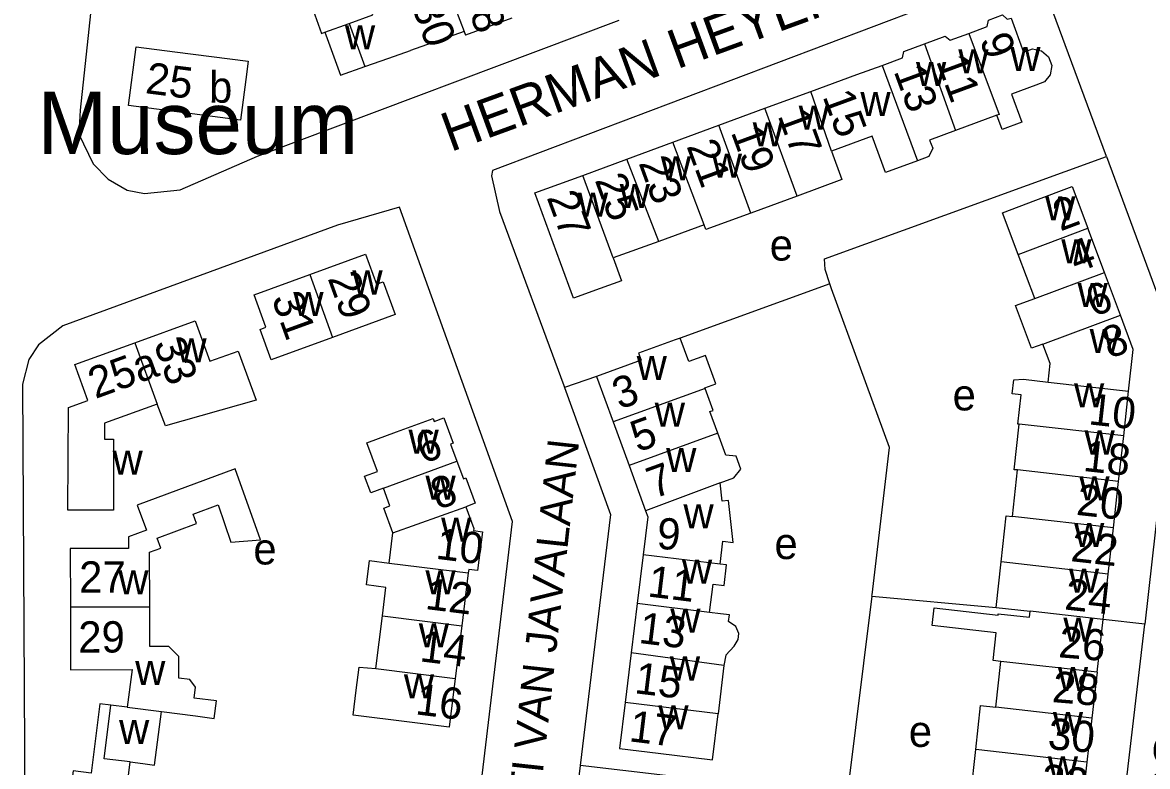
# Model space of a CAD drawing. Extents: x 161258 to 163262, y 380749 to 382054.
# Drawn here: x 161563.2 to 161707.1, y 381384.9 to 381480.1 of the extents above; entities that cross this region are included whole.
import ezdxf

# ---------------------------------------------------------------- set-up
doc = ezdxf.new("R2010")
doc.units = 0
for name, color, linetype in [('BLT_Basislijn', 7, 'Continuous'), ('BLT_Bebouwing', 7, 'Continuous'), ('BLT_Bebouwing_beschrifting', 7, 'Continuous'), ('BLT_Centroide', 7, 'Continuous'), ('BLT_Huisnummer', 7, 'Continuous'), ('BLT_Huisnummer_ tussenligend', 7, 'Continuous'), ('BLT_Onderverdeling_panden', 7, 'Continuous'), ('BLT_Straatnaam', 7, 'Continuous'), ('BLT_Straatnaam_verkleind', 7, 'Continuous')]:
    doc.layers.add(name, color=color, linetype=linetype)

msp = doc.modelspace()

# ---------------------------------------------------------------- linework, layer by layer
at = {"layer": 'BLT_Basislijn'}
for p, q in [((161666.45, 381446.68), (161647.33, 381439.73)), ((161636.63, 381434.83), (161632.51, 381433.43)), ((161671.84, 381406.71), (161687.71, 381405.27)), ((161706.75, 381403.16), (161701.39, 381403.74))]:
    msp.add_line(p, q, dxfattribs=at)
for points in [[(161647.76, 381582.3), (161646.86, 381582.41), (161591.08, 381589.63), (161587.77, 381589.77), (161586.23, 381588.91), (161584.89, 381586.68), (161583.08, 381574.39), (161573.92, 381500), (161570.58, 381468.89), (161570.42, 381465.8), (161572.24, 381462.03), (161574.18, 381460.03), (161576.58, 381458.66), (161578.81, 381458.22), (161583.37, 381458.7), (161593.26, 381463), (161639.49, 381480.37)], [(161701.85, 381462.93), (161692.96, 381486.95), (161678.18, 381481.89), (161623.33, 381461.17), (161623.17, 381460.48), (161624.21, 381455.92), (161632.42, 381433.68), (161632.51, 381433.43)], [(161666.45, 381446.68), (161665.84, 381448.48), (161665.78, 381449.87), (161701.85, 381462.93)], [(161701.85, 381462.93), (161710.73, 381438.82), (161706.75, 381403.16)], [(161619.38, 381362.01), (161625.85, 381416.26), (161611.4, 381456.47), (161603.5, 381454.17), (161568.37, 381441.3), (161565.27, 381438.88), (161564, 381436.97), (161563.2, 381433.85), (161563.56, 381371.71), (161565.42, 381369.4), (161568.4, 381368.11), (161592.1, 381365.28)], [(161671.84, 381406.71), (161671.86, 381406.88), (161674.07, 381425.72), (161666.67, 381446.04), (161666.45, 381446.68)], [(161632.51, 381433.43), (161638.42, 381417.16), (161634.53, 381385.07)], [(161671.84, 381406.71), (161668.65, 381381.35), (161667.24, 381381.25), (161634.53, 381385.07)], [(161634.53, 381385.07), (161631.61, 381361.46), (161631.65, 381360.05), (161700.74, 381351.9), (161706.75, 381403.16)]]:
    msp.add_lwpolyline(points, dxfattribs=at)
at = {"layer": 'BLT_Bebouwing'}
for p, q in [((161625.77, 381480.65), (161619.84, 381478.48)), ((161619.67, 381478.94), (161612.82, 381476.51)), ((161619.67, 381478.94), (161619.84, 381478.48)), ((161658.14, 381469.11), (161664.02, 381471.27)), ((161652.25, 381466.94), (161658.14, 381469.11)), ((161687.82, 381468.23), (161682.54, 381466.28)), ((161646.37, 381464.78), (161652.25, 381466.94)), ((161640.49, 381462.62), (161646.37, 381464.78)), ((161634.85, 381460.54), (161640.49, 381462.62)), ((161662.28, 381457.89), (161656.34, 381455.71)), ((161650.38, 381454.19), (161644.57, 381452.06)), ((161701.56, 381448.13), (161699.46, 381453.77)), ((161692.65, 381444.8), (161690.54, 381450.42)), ((161703.61, 381442.65), (161701.56, 381448.13)), ((161636.63, 381434.83), (161638.75, 381429.02)), ((161704.03, 381427.22), (161704.66, 381432.94)), ((161638.75, 381429.02), (161640.77, 381423.45)), ((161640.77, 381423.45), (161642.88, 381417.62)), ((161689.81, 381416.92), (161690.47, 381422.86)), ((161702.71, 381415.47), (161703.38, 381421.41)), ((161642.88, 381417.62), (161643.16, 381416.86)), ((161643.16, 381416.86), (161642.57, 381412.02)), ((161610.08, 381410.96), (161610.56, 381414.84)), ((161702.05, 381409.56), (161702.71, 381415.47)), ((161642.57, 381412.02), (161641.81, 381405.78)), ((161620.21, 381409.7), (161619.37, 381402.95)), ((161701.39, 381403.74), (161702.05, 381409.56)), ((161641.81, 381405.78), (161641.04, 381399.46)), ((161687.71, 381405.27), (161692.05, 381404.79)), ((161608.4, 381397.46), (161609.24, 381404.21)), ((161700.63, 381397.01), (161701.39, 381403.74)), ((161619.37, 381402.95), (161618.53, 381396.2)), ((161641.04, 381399.46), (161640.27, 381393.11)), ((161652.9, 381397.84), (161652.15, 381391.66)), ((161687.69, 381392.52), (161688.34, 381398.39)), ((161700.63, 381397.01), (161699.97, 381391.14)), ((161576.61, 381392.52), (161574.51, 381392.78)), ((161699.97, 381391.14), (161699.33, 381385.5)), ((161575.95, 381377.48), (161576.97, 381385.52))]:
    msp.add_line(p, q, dxfattribs=at)
for points in [[(161608.01, 381481.08), (161606.93, 381484.05), (161600.37, 381481.65), (161601.45, 381478.68), (161601.88, 381478.84)], [(161684.21, 381478.67), (161686.59, 381479.56), (161686.73, 381480.39), (161688.53, 381481.05), (161689.15, 381480.53), (161689.63, 381480.66), (161691.23, 381476.29)], [(161601.88, 381478.84), (161602.16, 381478.02), (161603.88, 381473.33), (161606.99, 381474.44)], [(161678.55, 381477.34), (161681.21, 381478.32), (161681.82, 381477.81), (161684.21, 381478.67)], [(161591.76, 381472.79), (161591.1, 381467.61), (161576.78, 381469.45), (161577.74, 381476.96), (161582.7, 381476.33), (161592.06, 381475.13), (161591.76, 381472.79)], [(161610.04, 381475.52), (161612.82, 381476.51)], [(161673.16, 381474.6), (161675.76, 381475.55), (161675.9, 381476.37), (161678.55, 381477.34)], [(161691.23, 381476.29), (161692.36, 381476.71), (161693.53, 381476.48), (161694.43, 381475.71), (161694.85, 381474.58), (161694.65, 381473.41), (161693.91, 381472.48), (161692.79, 381472.07), (161689.67, 381470.92), (161690.99, 381467.33), (161688.49, 381466.41), (161687.82, 381468.23)], [(161606.99, 381474.44), (161610.04, 381475.52)], [(161664.02, 381471.27), (161669.89, 381473.43), (161673.16, 381474.6)], [(161677.65, 381462.39), (161673.58, 381460.89), (161671.87, 381465.56), (161666.66, 381463.64)], [(161682.54, 381466.28), (161679.18, 381465.04), (161679.61, 381464.02), (161679.11, 381462.93), (161677.65, 381462.39)], [(161666.66, 381463.64), (161668, 381459.99), (161662.28, 381457.89)], [(161638.75, 381449.97), (161639.82, 381447.07), (161637.1, 381446.08), (161633.68, 381444.82), (161632.01, 381449.36), (161628.73, 381458.29), (161634.85, 381460.54)], [(161690.54, 381450.42), (161688.53, 381455.76), (161692.78, 381457.36), (161697.46, 381459.12), (161699.46, 381453.77)], [(161656.34, 381455.71), (161650.6, 381453.6), (161650.38, 381454.19)], [(161644.57, 381452.06), (161638.75, 381449.97)], [(161599.94, 381447.87), (161607.07, 381450.46), (161608.46, 381446.62), (161609.33, 381446.94), (161610.86, 381442.73), (161602.86, 381439.82)], [(161602.86, 381439.82), (161594.99, 381436.96), (161593.58, 381440.84), (161594.32, 381441.11), (161592.81, 381445.28), (161599.94, 381447.87)], [(161693.71, 381438.96), (161692.26, 381438.42), (161690.2, 381443.89), (161692.65, 381444.8)], [(161704.66, 381432.94), (161705.25, 381438.25), (161703.61, 381442.65)], [(161577.59, 381439.13), (161585.3, 381441.92), (161587, 381437.23), (161587.17, 381436.77), (161590.8, 381438.07), (161593.08, 381431.81), (161581.48, 381428.49), (161580.44, 381431.29)], [(161580.44, 381431.29), (161573.71, 381428.85), (161573.71, 381426.81), (161574.84, 381426.82), (161574.85, 381417.73), (161573.99, 381417.73), (161568.99, 381417.72), (161569.09, 381430.85), (161571.56, 381431.74), (161569.89, 381436.33), (161577.59, 381439.13)], [(161647.33, 381439.73), (161646.69, 381439.49), (161641.99, 381437.79), (161642.31, 381436.89), (161636.63, 381434.83)], [(161650.5, 381433.28), (161650.47, 381433.35), (161651.87, 381433.86), (161650.55, 381437.5), (161648.42, 381436.73), (161647.33, 381439.73)], [(161694.37, 381434.1), (161694.64, 381436.49), (161693.71, 381438.96)], [(161690.68, 381428.72), (161690.48, 381428.74), (161690.9, 381432.47), (161689.77, 381432.59), (161689.97, 381434.4), (161691.2, 381434.46), (161694.37, 381434.1)], [(161652.12, 381427.56), (161651.11, 381430.34), (161651.51, 381430.48), (161650.5, 381433.28)], [(161609.38, 381420.54), (161607.73, 381419.93), (161606.94, 381422.07), (161608.59, 381422.67), (161607.24, 381426.32), (161611.03, 381427.72), (161615.72, 381429.45), (161615.86, 381429.08), (161617.09, 381429.53), (161618.29, 381426.3), (161617.96, 381426.18), (161618.76, 381424)], [(161690.47, 381422.86), (161690.04, 381422.9), (161690.68, 381428.72)], [(161652.42, 381421.22), (161654.18, 381421.86), (161655.05, 381422.98), (161654.47, 381424.62), (161653.13, 381424.76), (161652.12, 381427.56)], [(161703.38, 381421.41), (161704.03, 381427.22)], [(161618.76, 381424), (161619.59, 381421.72), (161619.91, 381421.84), (161621.1, 381418.6), (161619.89, 381418.16)], [(161579.47, 381405.3), (161579.46, 381412.34), (161580.89, 381412.87), (161580.42, 381414.15), (161585.47, 381416.03), (161585.03, 381417.21), (161588.21, 381418.39), (161589.84, 381413.64), (161593.65, 381413.93), (161590.41, 381423.02), (161577.88, 381418.37), (161579.07, 381415.15), (161576.77, 381414.3), (161576.77, 381412.82), (161569.32, 381412.81), (161569.33, 381405.3)], [(161610.56, 381414.84), (161609.4, 381418), (161610.2, 381418.29), (161609.38, 381420.54)], [(161652.42, 381410.82), (161652.77, 381413.75), (161654.11, 381413.57), (161653.48, 381418.97), (161652.69, 381418.88), (161652.42, 381421.22)], [(161619.89, 381418.16), (161620.92, 381415.36), (161620.89, 381415.13)], [(161688.35, 381411.1), (161689.01, 381417.01), (161689.81, 381416.92)], [(161620.89, 381415.13), (161622.04, 381414.97), (161621.38, 381409.99), (161620.27, 381410.13), (161620.21, 381409.7)], [(161609.24, 381404.21), (161609.69, 381407.85), (161607.21, 381408.17), (161607.6, 381411.27), (161610.08, 381410.96)], [(161651.07, 381404.65), (161651.51, 381408.24), (161652.93, 381408.07), (161653.25, 381410.72), (161652.42, 381410.82)], [(161687.71, 381405.27), (161688.35, 381411.1)], [(161569.33, 381405.3), (161569.34, 381397.32), (161577.23, 381397.34), (161576.61, 381392.52)], [(161580.96, 381391.96), (161585.31, 381391.41), (161587.73, 381391.1), (161588.01, 381393.34), (161585.15, 381393.7), (161585.33, 381395.08), (161584.61, 381396.08), (161583.2, 381396.26), (161583.2, 381399.02), (161581.9, 381400.31), (161579.48, 381400.3), (161579.47, 381405.3)], [(161654.22, 381400.32), (161654.73, 381401.18), (161654.8, 381401.97), (161654.42, 381402.85), (161653.51, 381403.47), (161653.62, 381404.34), (161652.46, 381404.48), (161651.07, 381404.65)], [(161688.34, 381398.39), (161687.32, 381398.5), (161687.71, 381402.03), (161679.54, 381402.96), (161679.8, 381405.24), (161687.96, 381404.31), (161687.98, 381404.47), (161691.97, 381404.02), (161692.05, 381404.79)], [(161654.22, 381400.32), (161653.13, 381399.17), (161652.9, 381397.84)], [(161618.53, 381396.2), (161617.76, 381389.99), (161612.68, 381390.62), (161605.49, 381391.51), (161605.88, 381394.71), (161606.25, 381397.65), (161608.4, 381397.46)], [(161640.27, 381393.11), (161639.55, 381387.24), (161644.51, 381386.63), (161651.43, 381385.79), (161652.15, 381391.66)], [(161573.1, 381392.96), (161571.97, 381384.09), (161569.68, 381384.38), (161569.05, 381379.42), (161567.99, 381379.55), (161567.23, 381373.55), (161575.32, 381372.52), (161575.95, 381377.48)], [(161574.51, 381392.78), (161573.1, 381392.96)], [(161576.97, 381385.52), (161578.6, 381385.31), (161580.09, 381385.12), (161580.96, 381391.96)], [(161685.11, 381387.1), (161685.73, 381392.73), (161687.69, 381392.52)], [(161699.33, 381385.5), (161698.69, 381379.75), (161693.72, 381380.3), (161689.48, 381380.77), (161689.32, 381379.38), (161684.31, 381379.93), (161684.47, 381381.32), (161685.11, 381387.1)]]:
    msp.add_lwpolyline(points, dxfattribs=at)
at = {"layer": 'BLT_Onderverdeling_panden'}
for p, q in [((161615.23, 381490.73), (161619.67, 381478.94)), ((161604.97, 381479.97), (161606.99, 381474.44)), ((161678.55, 381477.34), (161682.54, 381466.28)), ((161673.16, 381474.6), (161677.65, 381462.39)), ((161666.66, 381463.64), (161664.02, 381471.27)), ((161662.28, 381457.89), (161658.14, 381469.11)), ((161656.34, 381455.71), (161652.25, 381466.94)), ((161650.38, 381454.19), (161646.37, 381464.78)), ((161644.57, 381452.06), (161640.49, 381462.62)), ((161638.75, 381449.97), (161634.85, 381460.54)), ((161690.54, 381450.42), (161699.46, 381453.77)), ((161599.94, 381447.87), (161602.86, 381439.82)), ((161692.65, 381444.8), (161701.56, 381448.13)), ((161693.71, 381438.96), (161703.61, 381442.65)), ((161577.59, 381439.13), (161580.44, 381431.29)), ((161694.37, 381434.1), (161704.66, 381432.94)), ((161650.5, 381433.28), (161638.75, 381429.02)), ((161652.12, 381427.56), (161640.77, 381423.45)), ((161609.38, 381420.54), (161618.76, 381424)), ((161703.38, 381421.41), (161690.47, 381422.86)), ((161652.42, 381421.22), (161642.88, 381417.62)), ((161610.56, 381414.84), (161619.89, 381418.16)), ((161702.71, 381415.47), (161689.81, 381416.92)), ((161652.42, 381410.82), (161642.57, 381412.02)), ((161610.08, 381410.96), (161620.21, 381409.7)), ((161702.05, 381409.56), (161688.35, 381411.1)), ((161579.47, 381405.3), (161569.33, 381405.3)), ((161651.07, 381404.65), (161641.81, 381405.78)), ((161701.39, 381403.74), (161692.05, 381404.79)), ((161609.24, 381404.21), (161619.37, 381402.95)), ((161652.9, 381397.84), (161641.04, 381399.46)), ((161608.4, 381397.46), (161618.53, 381396.2)), ((161700.63, 381397.01), (161688.34, 381398.39)), ((161652.15, 381391.66), (161640.27, 381393.11)), ((161576.61, 381392.52), (161580.96, 381391.96)), ((161699.97, 381391.14), (161687.69, 381392.52)), ((161699.33, 381385.5), (161685.11, 381387.1))]:
    msp.add_line(p, q, dxfattribs=at)
for points in [[(161604.97, 381479.97), (161608.01, 381481.08)], [(161601.88, 381478.84), (161604.97, 381479.97)], [(161684.21, 381478.67), (161688.1, 381468.33), (161687.82, 381468.23)], [(161704.03, 381427.22), (161690.68, 381428.72)], [(161576.97, 381385.52), (161573.64, 381385.94), (161574.51, 381392.78)]]:
    msp.add_lwpolyline(points, dxfattribs=at)

# ---------------------------------------------------------------- texts
at = {"layer": 'BLT_Bebouwing_beschrifting'}
msp.add_text('Museum', height=8, dxfattribs=at).set_placement((161565.11, 381463.26))
at = {"layer": 'BLT_Centroide'}
for s, p in [('w', (161604.44, 381476.66)), ('w', (161682.88, 381473.58)), ('w', (161689.53, 381473.89)), ('b', (161587.06, 381469.83)), ('w', (161677.47, 381471.97)), ('w', (161670.36, 381468.12)), ('w', (161662.47, 381466.39)), ('w', (161656.59, 381464.23)), ('w', (161644.83, 381459.91)), ('w', (161651.36, 381460.25)), ('w', (161639.58, 381456.38)), ('w', (161634.23, 381455.25)), ('w', (161693.99, 381454.78)), ('e', (161658.76, 381449.64)), ('w', (161696.05, 381449.28)), ('w', (161605.39, 381445.3)), ('w', (161698.13, 381443.72)), ('w', (161597.84, 381442.55)), ('w', (161699.68, 381437.81)), ('w', (161582.88, 381436.61)), ('w', (161641.75, 381434.38)), ('e', (161682.15, 381430.48)), ('w', (161697.68, 381430.88)), ('w', (161644.06, 381428.38)), ('w', (161612.57, 381424.94)), ('w', (161699.02, 381424.84)), ('w', (161574.72, 381422.27)), ('w', (161645.52, 381422.59)), ('w', (161614.74, 381419.06)), ('w', (161698.36, 381418.97)), ('w', (161647.73, 381415.39)), ('w', (161616.74, 381413.69)), ('w', (161697.69, 381413.03)), ('e', (161592.73, 381410.78)), ('e', (161659.37, 381411.47)), ('w', (161647.54, 381408.34)), ('w', (161575.45, 381406.94)), ('w', (161614.73, 381406.97)), ('w', (161697.03, 381407.19)), ('w', (161646.05, 381402.06)), ('w', (161613.88, 381400.19)), ('w', (161696.32, 381400.91)), ('w', (161645.99, 381395.94)), ('w', (161577.61, 381395.38)), ('w', (161695.61, 381394.59)), ('w', (161611.98, 381393.66)), ('w', (161644.52, 381389.69)), ('w', (161694.97, 381388.84)), ('w', (161575.55, 381387.84)), ('e', (161676.55, 381387.45)), ('w', (161694.32, 381383.16))]:
    msp.add_text(s, height=4, dxfattribs=at).set_placement(p)
at = {"layer": 'BLT_Huisnummer'}
for s, rotation, p in [('30', 290.072, (161612.95, 381482.2)), ('9', 290.2051, (161685.56, 381477.9)), ('25', 352.7106, (161578.81, 381471.06)), ('13', 290.2093, (161674.58, 381473.87)), ('15', 290.1996, (161665.49, 381470.65)), ('19', 290.1996, (161653.76, 381466.08)), ('23', 290.1972, (161641.96, 381462.14)), ('27', 290.1972, (161630.21, 381457.73)), ('2', 20.6173, (161695.93, 381453.35)), ('29', 289.974, (161602.2, 381447.39)), ('6', 20.6182, (161700.14, 381442.38)), ('31', 289.9566, (161595.02, 381444.82)), ('33', 289.9543, (161579.94, 381439.02)), ('25a', 19.9582, (161572.52, 381431.93)), ('3', 19.9221, (161639.55, 381430.56)), ('10', 353.6732, (161699.44, 381428.71)), ('6', 20.2073, (161614.41, 381423.6)), ('18', 353.6739, (161698.75, 381422.75)), ('7', 19.9236, (161643.94, 381419.16)), ('10', 352.9006, (161615.95, 381411.52)), ('22', 353.6685, (161697.16, 381411.21)), ('27', 0.0678, (161570.45, 381407.18)), ('11', 353.0472, (161643.04, 381406.7)), ('29', 0.1234, (161570.34, 381399.51)), ('26', 355.2278, (161695.61, 381398.92)), ('16', 352.9083, (161613.35, 381391.63)), ('17', 353.0512, (161640.67, 381388.18)), ('32', 353.6725, (161693.33, 381381.34))]:
    msp.add_text(s, height=4, rotation=rotation, dxfattribs=at).set_placement(p)
at = {"layer": 'BLT_Huisnummer_ tussenligend'}
for s, rotation, p in [('28', 290.0725, (161619.34, 381484)), ('11', 290.2051, (161680, 381475.18)), ('17', 290.1996, (161659.75, 381468.2)), ('21', 290.1996, (161648.09, 381464.29)), ('25', 290.1972, (161636.36, 381459.95)), ('4', 20.6173, (161697.96, 381448.02)), ('8', 20.6182, (161702.2, 381437.05)), ('5', 19.9221, (161641.87, 381425.09)), ('8', 20.2073, (161616.33, 381417.73)), ('20', 353.6739, (161697.87, 381417.14)), ('9', 355.9236, (161644.24, 381412.8)), ('12', 352.9006, (161614.6, 381405.1)), ('24', 353.6685, (161696.37, 381405.04)), ('13', 353.0472, (161641.91, 381400.75)), ('14', 352.9006, (161613.9, 381398.41)), ('15', 353.0472, (161641.37, 381394.33)), ('28', 355.2278, (161694.8, 381393.19)), ('30', 355.2278, (161694.24, 381387.18))]:
    msp.add_text(s, height=4, rotation=rotation, dxfattribs=at).set_placement(p)
at = {"layer": 'BLT_Straatnaam'}
for s, rotation, p in [('HERMAN HEYERMANSLAAN', 20.0858, (161617.95, 381463.5)), ('JACQUES PERKSTRAAT', 83.2287, (161711.11, 381371.59))]:
    msp.add_text(s, height=5, rotation=rotation, dxfattribs=at).set_placement(p)
at = {"layer": 'BLT_Straatnaam_verkleind'}
msp.add_text('MELATI VAN JAVALAAN', height=4, rotation=83.7423, dxfattribs=at).set_placement((161627.79, 381366.27))

doc.saveas('drawing.dxf')
